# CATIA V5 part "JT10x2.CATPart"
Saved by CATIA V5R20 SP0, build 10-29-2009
Part number: JT10x2
Revision: ANY
Definition: UNKNOWN
Nomenclature: JT10x2
Source: Unknown
Bounding box of the stored display mesh (mm): x -6.824 to 6.824, y -1 to 1, z -7 to 7
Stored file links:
  C:\Users\Utente\Desktop\IO LAVORO\3D X SITO CF\CUMSA\3D files SA\SA 160016\JT10x2.CATPart
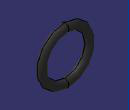
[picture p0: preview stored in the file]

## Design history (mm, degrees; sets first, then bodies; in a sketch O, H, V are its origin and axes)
Body1 "Revolución1" (main body)
  Solid1: solid without history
